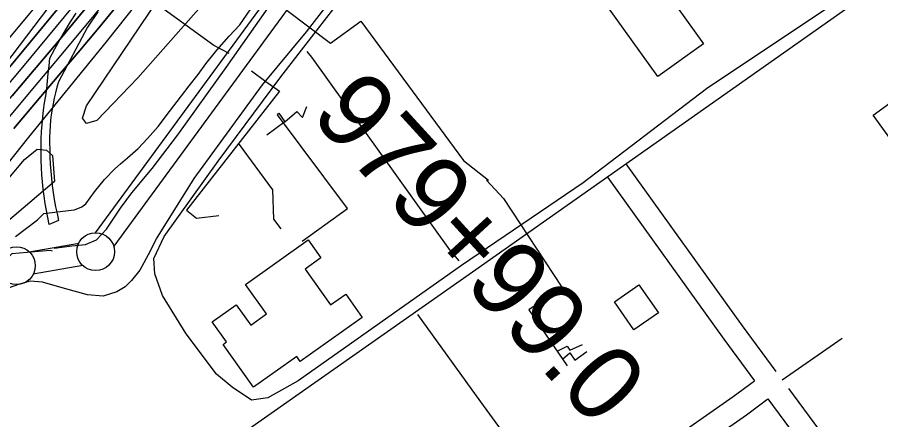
# Model space of a CAD drawing. Extents: x 3677843 to 3715951, y 511991 to 537744.
# Drawn here: x 3683314 to 3684455, y 518941 to 519472 of the extents above; entities that cross this region are included whole.
import ezdxf

# ---------------------------------------------------------------- set-up
doc = ezdxf.new("R2010")
doc.units = 0
for name, color, linetype in [('V-BLDG-OTLN', 7, 'Continuous'), ('V-CHAN-DOCK', 7, 'Continuous'), ('V-FLOD-BASE', 7, 'Continuous'), ('V-LEVE-TOET', 7, 'Continuous'), ('V-RIVR-EDGE', 7, 'Continuous'), ('V-RIVR-FERY', 7, 'Continuous'), ('V-ROAD-CNTR', 7, 'Continuous'), ('V-RRAP-RVMT', 7, 'Continuous'), ('V-SITE-OTLN', 7, 'Continuous'), ('V-SITE-VEGE', 7, 'Continuous'), ('V-SURV-IDEN', 7, 'Continuous'), ('V-SURV-LINE', 7, 'Continuous'), ('V-TOPO-DPTH', 7, 'Continuous'), ('V-TOPO-MINR', 7, 'Continuous'), ('V-TOPO-WATR', 7, 'Continuous'), ('V-UTIL-LINE', 7, 'Continuous')]:
    doc.layers.add(name, color=color, linetype=linetype)

msp = doc.modelspace()

# ---------------------------------------------------------------- linework, layer by layer
at = {"layer": 'V-BLDG-OTLN'}
for points in [[(3683927.9, 519717.9), (3683988.2, 519761.3), (3684221, 519437.4), (3684160.6, 519394)], [(3684811.4, 519077.5), (3684697.8, 518995.1), (3684445.1, 519343.3), (3684538.3, 519410.9), (3684505.9, 519455.6), (3684516.8, 519463.5), (3684489.1, 519501.6), (3684583.6, 519570.1), (3684612, 519531), (3684651, 519559.3), (3684763.1, 519404.8), (3684741.1, 519388.8), (3684747.6, 519379.9), (3684687.1, 519336), (3684680, 519345.7), (3684659.7, 519331), (3684587.7, 519430.3), (3684566.4, 519414.9)], [(3683747.9, 519106.9), (3683769.7, 519076.2), (3683687.8, 519017.9), (3683683, 519024.6), (3683625.9, 518984), (3683585.7, 519040.5), (3683590.3, 519043.8), (3683571.3, 519070.4), (3683603, 519092.9), (3683622.2, 519066), (3683643, 519080.8), (3683615.5, 519119.5), (3683698.2, 519178.4), (3683715.1, 519154.6), (3683694.4, 519139.9), (3683727.9, 519092.7)], [(3684135.5, 519119.3), (3684161.3, 519082.2), (3684128.8, 519059.7), (3684103, 519096.7)]]:
    msp.add_lwpolyline(points, close=True, dxfattribs=at)
at = {"layer": 'V-CHAN-DOCK'}
for points in [[(3683420.3, 519479.7), (3683406.4, 519459.4), (3683368.2, 519387), (3683366, 519379.9), (3683364.1, 519372.8), (3683362.4, 519365.6), (3683360.9, 519358.3), (3683359.6, 519351.1), (3683358.6, 519343.7), (3683357.7, 519336.4), (3683357.1, 519329), (3683356.6, 519321.7), (3683356.4, 519314.3), (3683356.4, 519306.9), (3683356.5, 519297.4), (3683356.7, 519288), (3683357.2, 519278.5), (3683357.9, 519269.1), (3683358.8, 519259.7), (3683359.9, 519250.3), (3683361.1, 519241), (3683362.6, 519231.6), (3683364.3, 519222.3), (3683366.2, 519213.1), (3683368.3, 519203.9), (3683355.9, 519198.7)], [(3683355.9, 519198.7), (3683353.9, 519208), (3683352.1, 519217.3), (3683350.5, 519226.7), (3683349.1, 519236.1), (3683347.9, 519245.5), (3683346.9, 519255), (3683346.1, 519264.5), (3683345.6, 519274), (3683345.2, 519283.5), (3683345.1, 519293), (3683345.1, 519302.5), (3683345.4, 519312), (3683345.8, 519321.5), (3683346.5, 519331), (3683347.4, 519340.4), (3683348.5, 519349.9), (3683349.7, 519359.3), (3683351.2, 519368.7), (3683352.9, 519378), (3683353.6, 519388.1), (3683354.5, 519398.2), (3683355.6, 519408.3), (3683356.9, 519418.3), (3683363.4, 519430.5), (3683370.1, 519442.5), (3683377, 519454.4), (3683384.1, 519466.2), (3683391.4, 519477.8)]]:
    msp.add_lwpolyline(points, dxfattribs=at)
at = {"layer": 'V-FLOD-BASE'}
msp.add_line((3683362.5, 519167.5), (3683382.5, 519170.2), dxfattribs=at)
msp.add_lwpolyline([(3683381.5, 519170.2), (3683403.8, 519172.5), (3683418.3, 519178.5), (3683431.7, 519192.5), (3683450, 519220.3), (3683465, 519240.8), (3683491.8, 519272.6), (3683525.9, 519317.2), (3683589.6, 519406.1), (3683650.6, 519492.2), (3683730.1, 519593.1), (3683778.8, 519652.6), (3683844.5, 519728.2), (3683902.2, 519805)], dxfattribs=at)
at = {"layer": 'V-LEVE-TOET'}
for points in [[(3683489.5, 519163.4), (3683497.9, 519179.7), (3683547.5, 519259.7), (3683637.6, 519383.2), (3683696.1, 519453.2), (3683782.5, 519565), (3683862.5, 519669.9), (3683883.2, 519700.1), (3683890.9, 519712.2), (3683899.5, 519724.6), (3683931.9, 519766.1), (3683986.7, 519837.6), (3684033.4, 519886.7), (3684061.8, 519916.8), (3684073.9, 519926.8), (3684084.8, 519935.7)], [(3683384.7, 519217.7), (3683389.2, 519218), (3683399, 519222.1), (3683404.2, 519226.2), (3683415.7, 519241.8), (3683428.9, 519258), (3683442.8, 519272.5), (3683450.1, 519279), (3683459.5, 519286.6), (3683473.4, 519299), (3683486, 519312.4), (3683499.9, 519328.3), (3683514.9, 519348), (3683540.7, 519381.8), (3683552.8, 519397), (3683563, 519410.8), (3683577.6, 519428.8), (3683593.9, 519447.4), (3683607.9, 519462.6), (3683622.5, 519483.6)], [(3683311.1, 519183), (3683340.3, 519205), (3683348.6, 519213.2), (3683384.7, 519217.7)], [(3683489.5, 519163.4), (3683475.6, 519138.6), (3683464.5, 519124.8), (3683456.2, 519116.6), (3683445.1, 519109.7), (3683427.1, 519104.3), (3683406.4, 519105.8), (3683376.1, 519114.2), (3683347.1, 519122.6), (3683330.5, 519124.1), (3683316.7, 519120), (3683300.1, 519114.5), (3683191.8, 518996.2), (3683181.4, 518980.1)]]:
    msp.add_lwpolyline(points, dxfattribs=at)
at = {"layer": 'V-RIVR-EDGE'}
msp.add_lwpolyline([(3683281.5, 519254.9), (3683329.1, 519314.2), (3683431.5, 519440), (3683498.3, 519523.9), (3683577.9, 519643.7), (3683632.1, 519725.3), (3683692.9, 519786.3), (3683762.7, 519860), (3683803.1, 519913.3), (3683830.1, 519941.5), (3683872.8, 519964.2), (3683912.6, 520007.3), (3683936.1, 520068.5), (3683978.3, 520149.4), (3684010.3, 520188.4), (3684114.4, 520288.4), (3684184.2, 520354.8), (3684214.9, 520407.6), (3684229.4, 520461), (3684277.6, 520516.7), (3684326.4, 520572.4)], dxfattribs=at)
at = {"layer": 'V-RIVR-FERY'}
msp.add_spline([(3683395.6, 529471.3), (3683521.9, 529210.1), (3683605.1, 528969.7), (3683680.8, 528445.2), (3683751.5, 527893.7), (3683927.9, 527005.7), (3684042.4, 526379.7), (3684112.2, 525834.6), (3684119.2, 525226.8), (3684092.5, 524348.2), (3684041.6, 523650.6), (3683951.4, 522948.6), (3683790.8, 522287.1), (3683653.8, 521935.8), (3683329.6, 521213.6), (3682839.7, 520457.3), (3682512.6, 519997.8), (3682286.2, 519636), (3682113.5, 519264), (3682089.8, 519186.3)], degree=3, dxfattribs=at)
at = {"layer": 'V-ROAD-CNTR'}
for points in [[(3682174.1, 517894.3), (3682399.3, 518065.1), (3682591.5, 518209.7), (3682681.9, 518278.9), (3682777.5, 518341), (3682917.9, 518436.4), (3682969.7, 518473.9), (3683256.3, 518673.1), (3683557.4, 518885.5), (3683915.2, 519136.1), (3684420.6, 519491.5), (3684682.9, 519677.5), (3684705.4, 519694.9), (3684721.5, 519707.8), (3684735.1, 519717.4), (3684750.9, 519733.1), (3684765.4, 519753.2), (3684781.2, 519774.7), (3684805.9, 519807.7), (3684938.2, 520041.4), (3685073, 520275.9), (3685424.6, 520876.4)], [(3684118.2, 519279), (3684271.7, 519065.1), (3684316.4, 519004.7)], [(3684093.9, 519261.5), (3684247.5, 519047.4), (3684288, 518992.6)], [(3684035.6, 518815), (3683926.4, 518964.8), (3683843.3, 519080)], [(3684324.7, 518993.5), (3684404.2, 519048.7)], [(3684047.2, 518823.1), (3684260, 518971.9), (3684288, 518992.6)], [(3684333, 518982.2), (3684427.4, 518854.6), (3684633.1, 518565.2)], [(3684105, 518826.9), (3684277.5, 518947.6), (3684305.8, 518968.5)], [(3684305.8, 518968.5), (3684403.1, 518837), (3684608.7, 518547.8)]]:
    msp.add_lwpolyline(points, dxfattribs=at)
at = {"layer": 'V-RRAP-RVMT'}
msp.add_line((3683377.8, 519516.4), (3683296.7, 519409.1), dxfattribs=at)
at = {"layer": 'V-SITE-OTLN'}
msp.add_lwpolyline([(3684391.6, 519489.1), (3684224.6, 519377.8), (3684061.6, 519253.6), (3683901, 519144.5), (3683685, 518992.2), (3683644.8, 518970), (3683623.1, 518966.8), (3683597.5, 518984.2), (3683577, 519001.2), (3683536.8, 519054.6), (3683505.4, 519105.1), (3683495.3, 519133.8), (3683494.3, 519154), (3683508, 519183), (3683579.4, 519282.6), (3683662.2, 519393.9), (3683770.1, 519533.4)], dxfattribs=at)
at = {"layer": 'V-SITE-VEGE'}
for points in [[(3683883.2, 519896.1), (3683606.8, 519544.2), (3683472.8, 519392.3), (3683419, 519336.2), (3683405.2, 519332.1), (3683399.7, 519339), (3683405.3, 519355.5), (3683499.4, 519495.2), (3683587.8, 519603.4), (3683644.5, 519670.4), (3683730.1, 519760.7), (3683801.9, 519842.9), (3683839.2, 519883.9), (3683861.3, 519911.3), (3683869.6, 519919.5)], [(3683362.9, 519255.5), (3683267.8, 519174.9), (3683180.8, 519086), (3683121.4, 519020.3), (3683104.8, 518984.7), (3683096.5, 518980.6), (3683088.3, 518984.7), (3683093.8, 518998.4), (3683116, 519040.9), (3683179.6, 519117.6), (3683250, 519192.9), (3683302.5, 519259.9), (3683323.2, 519284.6), (3683339.8, 519298.2), (3683352.1, 519296.8), (3683360.3, 519289.9)]]:
    msp.add_lwpolyline(points, close=True, dxfattribs=at)
at = {"layer": 'V-SURV-LINE'}
for points in [[(3683416.9, 519187.9), (3683652.3, 519508.6)], [(3683676.5, 519490.8), (3683441.1, 519170.1)], [(3683329.5, 519162.6), (3683394.9, 519174.2)], [(3683400.1, 519144.7), (3683334.8, 519133.1)]]:
    msp.add_lwpolyline(points, dxfattribs=at)
for centre in [(3683417.2, 519162.9), (3683312.5, 519144.4)]:
    msp.add_circle(centre, 25, dxfattribs=at)
at = {"layer": 'V-TOPO-DPTH'}
for points in [[(3684318.7, 520619.4), (3684245.9, 520512), (3684242.1, 520506.6), (3684238.3, 520501.2), (3684234.4, 520495.9), (3684230.5, 520490.7), (3684056.7, 520265.5), (3683966, 520148.3), (3683875.2, 520031.3), (3683784, 519914.5), (3683692.6, 519797.9), (3683553.2, 519620.7), (3683531.3, 519592.9), (3683509.1, 519565.3), (3683486.8, 519537.7), (3683464.4, 519510.3), (3683441.8, 519483), (3683419.2, 519455.8), (3683396.4, 519428.7), (3683373.5, 519401.7), (3683308.9, 519325.6)], [(3682090.3, 518329.5), (3682090.6, 518303.5), (3682194.3, 518374.3), (3682308.3, 518454.9), (3682421.4, 518536.7), (3682627.9, 518688.8), (3682636.8, 518695.7), (3682645.5, 518703), (3682653.9, 518710.7), (3682661.9, 518718.7), (3682787.5, 518849.8), (3682857.4, 518924.3), (3682926.2, 518999.6), (3682993.5, 519076.4), (3683059.8, 519154.1), (3683448, 519618.5), (3684153, 520546.4)], [(3682090.6, 518303.5), (3682194.3, 518374.3), (3682308.3, 518454.9), (3682421.4, 518536.7), (3682627.9, 518688.8), (3682636.8, 518695.7), (3682645.5, 518703), (3682653.9, 518710.7), (3682661.9, 518718.7), (3682787.5, 518849.8), (3682857.4, 518924.3), (3682926.2, 518999.6), (3682993.5, 519076.4), (3683059.8, 519154.1), (3683448, 519618.5), (3684153, 520546.4)], [(3682090.9, 518280.6), (3682154.5, 518326.5), (3682626.1, 518673.4), (3682639.5, 518683.8), (3682652.6, 518694.7), (3682665, 518706.2), (3682677.1, 518718.2), (3682879, 518928.6), (3682981, 519037.2), (3683081.4, 519147.3), (3683179.3, 519259.6), (3683275.6, 519373.4), (3683450.7, 519584.9), (3683458.2, 519594), (3683465.7, 519603.1), (3683473.1, 519612.3), (3683480.4, 519621.6), (3683610.6, 519786.3), (3683682.5, 519878.2), (3683753.9, 519970.7), (3683824.2, 520063.8), (3683894, 520157.4), (3684157.4, 520514.7), (3684169.1, 520530.8)], [(3684169.1, 520530.8), (3684157.4, 520514.7), (3683894, 520157.4), (3683824.2, 520063.8), (3683753.9, 519970.7), (3683682.5, 519878.2), (3683610.6, 519786.3), (3683480.4, 519621.6), (3683473.1, 519612.3), (3683465.7, 519603.1), (3683458.2, 519594), (3683450.7, 519584.9), (3683275.6, 519373.4)], [(3682091, 518266.2), (3682624.3, 518658), (3682642.2, 518671.9), (3682659.6, 518686.4), (3682676.2, 518701.7), (3682692.4, 518717.7), (3683118.5, 519160.8), (3683182.6, 519229), (3683245.6, 519298.2), (3683307.1, 519368.8), (3683367.5, 519440.3), (3683454, 519545.2), (3683470.3, 519565), (3683486.5, 519585), (3683502.5, 519605.1), (3683518.4, 519625.3), (3683971.8, 520205.3), (3684012.3, 520257.8), (3684052.2, 520310.7), (3684091.5, 520364.1), (3684130.2, 520418), (3684164.8, 520466.8), (3684185.6, 520496.6), (3684206.1, 520526.7)], [(3684206.1, 520526.7), (3684185.6, 520496.6), (3684164.8, 520466.8), (3684130.2, 520418), (3684091.5, 520364.1), (3684052.2, 520310.7), (3684012.3, 520257.8), (3683971.8, 520205.3), (3683518.4, 519625.3), (3683502.5, 519605.1), (3683486.5, 519585), (3683470.3, 519565), (3683454, 519545.2), (3683367.5, 519440.3), (3683307.1, 519368.8)]]:
    msp.add_lwpolyline(points, dxfattribs=at)
at = {"layer": 'V-TOPO-MINR'}
for points in [[(3682090.6, 518303.5), (3682194.3, 518374.3), (3682308.3, 518454.9), (3682421.4, 518536.7), (3682627.9, 518688.8), (3682636.8, 518695.7), (3682645.5, 518703), (3682653.9, 518710.7), (3682661.9, 518718.7), (3682787.5, 518849.8), (3682857.4, 518924.3), (3682926.2, 518999.6), (3682993.5, 519076.4), (3683059.8, 519154.1), (3683448, 519618.5), (3684153, 520546.4)], [(3682090.9, 518280.6), (3682154.5, 518326.5), (3682626.1, 518673.4), (3682639.5, 518683.8), (3682652.6, 518694.7), (3682665, 518706.2), (3682677.1, 518718.2), (3682879, 518928.6), (3682981, 519037.2), (3683081.4, 519147.3), (3683179.3, 519259.6), (3683275.6, 519373.4), (3683450.7, 519584.9), (3683458.2, 519594), (3683465.7, 519603.1), (3683473.1, 519612.3), (3683480.4, 519621.6), (3683610.6, 519786.3), (3683682.5, 519878.2), (3683753.9, 519970.7), (3683824.2, 520063.8), (3683894, 520157.4), (3684157.4, 520514.7), (3684169.1, 520530.8)], [(3682091, 518273), (3682625.2, 518665.7), (3682640.8, 518677.9), (3682656.1, 518690.5), (3682670.6, 518704), (3682684.8, 518717.9), (3682997.5, 519043.5), (3683080.8, 519132.2), (3683162.7, 519222), (3683242.5, 519313.7), (3683321, 519406.6), (3683452.4, 519565.5), (3683464.1, 519579.9), (3683475.8, 519594.3), (3683487.4, 519608.8), (3683498.9, 519623.4), (3683754.3, 519948.4), (3683829.3, 520045), (3683903.6, 520142.3), (3683976.7, 520240.4), (3684049.1, 520339.1), (3684160.6, 520493.2), (3684176.5, 520515.4), (3684192.1, 520537.8)], [(3683290.1, 519325.6), (3683332.1, 519375.1), (3683373.8, 519424.9), (3683415.3, 519474.9), (3683455.8, 519524), (3683476.7, 519549.6), (3683497.5, 519575.4), (3683518.1, 519601.3), (3683538.5, 519627.3), (3684185.8, 520458.9), (3684192.5, 520467.6), (3684199.1, 520476.4), (3684205.5, 520485.3), (3684211.8, 520494.3), (3684218, 520503.4), (3684224.1, 520512.5), (3684230, 520521.7), (3684235.9, 520531)], [(3682091, 518266.2), (3682624.3, 518658), (3682642.2, 518671.9), (3682659.6, 518686.4), (3682676.2, 518701.7), (3682692.4, 518717.7), (3683118.5, 519160.8), (3683182.6, 519229), (3683245.6, 519298.2), (3683307.1, 519368.8), (3683367.5, 519440.3), (3683454, 519545.2), (3683470.3, 519565), (3683486.5, 519585), (3683502.5, 519605.1), (3683518.4, 519625.3), (3683971.8, 520205.3), (3684012.3, 520257.8), (3684052.2, 520310.7), (3684091.5, 520364.1), (3684130.2, 520418), (3684164.8, 520466.8), (3684185.6, 520496.6), (3684206.1, 520526.7)]]:
    msp.add_lwpolyline(points, dxfattribs=at)
at = {"layer": 'V-TOPO-WATR'}
msp.add_lwpolyline([(3683308.9, 519325.6), (3683373.5, 519401.7), (3683396.4, 519428.7), (3683419.2, 519455.8), (3683441.8, 519483), (3683464.4, 519510.3), (3683486.8, 519537.7), (3683509.1, 519565.3), (3683531.3, 519592.9), (3683553.2, 519620.7), (3683692.6, 519797.9), (3683784, 519914.5), (3683875.2, 520031.3), (3683966, 520148.3), (3684056.7, 520265.5), (3684230.5, 520490.7), (3684234.4, 520495.9), (3684238.3, 520501.2), (3684242.1, 520506.6), (3684245.9, 520512), (3684318.7, 520619.4)], dxfattribs=at)
at = {"layer": 'V-UTIL-LINE'}
msp.add_line((3683667.2, 519334.2), (3683643.4, 519316.7), dxfattribs=at)
for points in [[(3683593.7, 519424.4), (3683573.3, 519434.9), (3683449.9, 519524.7)], [(3683670.3, 519481.4), (3683727.5, 519438), (3683768, 519467.2), (3683903.3, 519283.5), (3683936.4, 519257.3), (3683934, 519257.3), (3683956.6, 519233), (3684033.4, 519115.9), (3684032, 519115), (3683989.7, 519086.3), (3684040.6, 519012)], [(3683897.9, 519150.7), (3683885.6, 519165.5), (3683703.2, 519419.6), (3683697, 519427.3)], [(3683623.4, 519401.5), (3683642.3, 519387.7), (3683660.3, 519374.8), (3683537.2, 519217.8), (3683550.4, 519207.3), (3683580.3, 519210.5)], [(3683657.7, 519343.7), (3683659.6, 519345.6), (3683667.2, 519334.2), (3683683.4, 519347.9), (3683690.9, 519340.2), (3683696.2, 519354.4)], [(3683690.2, 519176.6), (3683750.1, 519220), (3683657.7, 519343.7)], [(3683662.3, 519193.1), (3683652.9, 519205.9), (3683651.6, 519244.4), (3683606.3, 519306.2), (3683606.3, 519306)], [(3683360.4, 519163.4), (3683357, 519164.4), (3683306.3, 519159.9), (3683140.9, 518989.8), (3683135, 518955.7)], [(3684027.2, 519031.4), (3684040.6, 519038), (3684043.9, 519032.8), (3684061, 519040.3)], [(3684034.2, 519021.2), (3684044.2, 519029.2), (3684050.8, 519019.7), (3684066.6, 519031)]]:
    msp.add_lwpolyline(points, dxfattribs=at)

# ---------------------------------------------------------------- texts
at = {"layer": 'V-SURV-IDEN'}
msp.add_text('979+99.0', height=100, rotation=312.4787, dxfattribs=at).set_placement((3683699.3, 519342.3))

doc.saveas('drawing.dxf')
